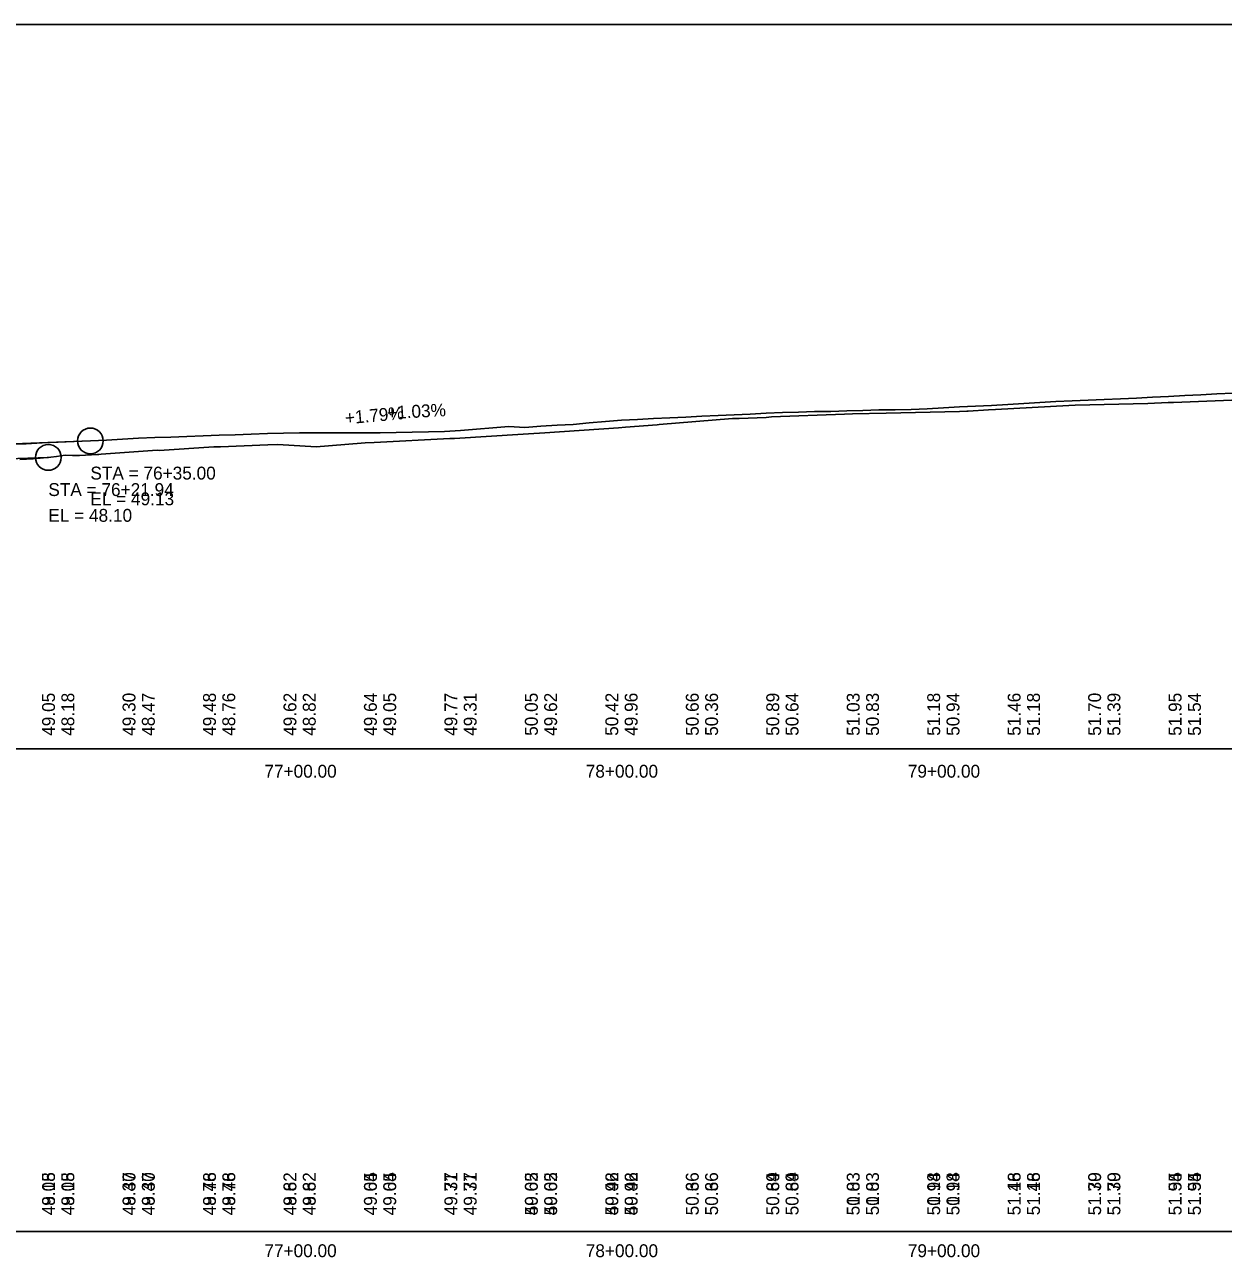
# Model space of a CAD drawing. Extents: x 3880794 to 3915434, y 287517 to 300173.
# Drawn here: x 3888152.9 to 3888525.3, y 297716.1 to 298099.2 of the extents above; entities that cross this region are included whole.
import ezdxf

# ---------------------------------------------------------------- set-up
doc = ezdxf.new("R2010")
doc.units = 0
for name, color, linetype in [('Level 1', 7, 'Continuous'), ('Level 2', 7, 'Continuous'), ('Level 30', 7, 'Continuous'), ('Level 31', 7, 'Continuous'), ('Level 32', 7, 'Continuous'), ('Level 62', 7, 'Continuous'), ('Level 63', 7, 'Continuous')]:
    doc.layers.add(name, color=color, linetype=linetype)

msp = doc.modelspace()

# ---------------------------------------------------------------- linework, layer by layer
at = {"layer": 'Level 1'}
for p, q in [((3888454.51, 297979.57), (3888477.27, 297980.88)), ((3888477.27, 297980.88), (3888479.27, 297980.91)), ((3888479.27, 297980.91), (3888501.82, 297981.48)), ((3888501.82, 297981.48), (3888508.1, 297981.73)), ((3888508.1, 297981.73), (3888509.82, 297981.78)), ((3888509.82, 297981.78), (3888533.14, 297982.7)), ((3888350.03, 297974.92), (3888372.84, 297976.79)), ((3888372.84, 297976.79), (3888374.91, 297976.82)), ((3888374.91, 297976.82), (3888383.28, 297977.13)), ((3888383.28, 297977.13), (3888384.96, 297977.28)), ((3888384.96, 297977.28), (3888407.59, 297978.13)), ((3888407.59, 297978.13), (3888410.04, 297978.24)), ((3888410.04, 297978.24), (3888420.58, 297978.5)), ((3888420.58, 297978.5), (3888443.34, 297979.03)), ((3888443.34, 297979.03), (3888445.58, 297979.08)), ((3888445.58, 297979.08), (3888446.03, 297979.09)), ((3888446.03, 297979.09), (3888452.37, 297979.45)), ((3888452.37, 297979.45), (3888454.51, 297979.57)), ((3888309.37, 297972.01), (3888314.47, 297972.36)), ((3888314.47, 297972.36), (3888337.33, 297973.92)), ((3888337.33, 297973.92), (3888339.57, 297974.08)), ((3888339.57, 297974.08), (3888349.44, 297974.88)), ((3888349.44, 297974.88), (3888350.03, 297974.92)), ((3888213.77, 297967.97), (3888228.46, 297968.58)), ((3888228.46, 297968.58), (3888231.56, 297968.71)), ((3888231.56, 297968.71), (3888243.46, 297968)), ((3888243.46, 297968), (3888257.41, 297969.12)), ((3888257.41, 297969.12), (3888258.68, 297969.19)), ((3888258.68, 297969.19), (3888261.5, 297969.34)), ((3888261.5, 297969.34), (3888284.97, 297970.56)), ((3888284.97, 297970.56), (3888286.46, 297970.6)), ((3888286.46, 297970.6), (3888307.75, 297971.91)), ((3888307.75, 297971.91), (3888309.37, 297972.01)), ((3888138.3, 297963.97), (3888160.24, 297964.71)), ((3888160.24, 297964.71), (3888161.02, 297964.78)), ((3888161.02, 297964.78), (3888162.78, 297965.02)), ((3888162.78, 297965.02), (3888165.44, 297965.39)), ((3888165.44, 297965.39), (3888167.71, 297965.28)), ((3888167.71, 297965.28), (3888168.39, 297965.32)), ((3888168.39, 297965.32), (3888169.57, 297965.28)), ((3888169.57, 297965.28), (3888169.87, 297965.29)), ((3888169.87, 297965.29), (3888175.48, 297965.6)), ((3888175.48, 297965.6), (3888175.94, 297965.66)), ((3888175.94, 297965.66), (3888176.69, 297965.72)), ((3888176.69, 297965.72), (3888194.04, 297966.95)), ((3888194.04, 297966.95), (3888194.67, 297966.89)), ((3888194.67, 297966.89), (3888211.62, 297967.97)), ((3888211.62, 297967.97), (3888213.77, 297967.97))]:
    msp.add_line(p, q, dxfattribs=at)
for points in [[(3888213.77, 297967.97), (3888228.46, 297968.58), (3888231.56, 297968.71), (3888243.46, 297968), (3888257.41, 297969.12), (3888258.68, 297969.19), (3888261.5, 297969.34), (3888284.97, 297970.56), (3888286.46, 297970.6), (3888307.75, 297971.91), (3888309.37, 297972.01), (3888314.47, 297972.36), (3888337.33, 297973.92), (3888339.57, 297974.08), (3888349.44, 297974.88), (3888350.03, 297974.92), (3888372.84, 297976.79), (3888374.91, 297976.82), (3888383.28, 297977.13), (3888384.96, 297977.28), (3888407.59, 297978.13), (3888410.04, 297978.24), (3888420.58, 297978.5), (3888443.34, 297979.03), (3888445.58, 297979.08), (3888446.03, 297979.09), (3888452.37, 297979.45), (3888454.51, 297979.57), (3888477.27, 297980.88), (3888479.27, 297980.91), (3888501.82, 297981.48), (3888508.1, 297981.73), (3888509.82, 297981.78), (3888533.14, 297982.7)], [(3888151.4, 297964.06), (3888155.49, 297964.25), (3888156.52, 297964.37), (3888161.02, 297964.78), (3888162.78, 297965.02), (3888165.44, 297965.39), (3888167.71, 297965.28), (3888168.39, 297965.32), (3888169.57, 297965.28), (3888169.87, 297965.29), (3888175.48, 297965.6), (3888175.94, 297965.66), (3888176.69, 297965.72), (3888194.04, 297966.95), (3888194.67, 297966.89), (3888211.62, 297967.97), (3888213.77, 297967.97)]]:
    msp.add_lwpolyline(points, dxfattribs=at)
msp.add_circle((3888160.24, 297964.71), 4, dxfattribs=at)
at = {"layer": 'Level 2'}
for p, q in [((3888508.3, 297983.67), (3888513.3, 297983.93)), ((3888513.3, 297983.93), (3888518.3, 297984.18)), ((3888518.3, 297984.18), (3888523.3, 297984.43)), ((3888523.3, 297984.43), (3888528.3, 297984.69)), ((3888433.3, 297979.79), (3888438.3, 297980.07)), ((3888438.3, 297980.07), (3888443.3, 297980.39)), ((3888443.3, 297980.39), (3888448.3, 297980.68)), ((3888448.3, 297980.68), (3888453.3, 297980.89)), ((3888453.3, 297980.89), (3888458.3, 297981.15)), ((3888458.3, 297981.15), (3888463.3, 297981.47)), ((3888463.3, 297981.47), (3888468.3, 297981.79)), ((3888468.3, 297981.79), (3888473.3, 297982.08)), ((3888473.3, 297982.08), (3888478.3, 297982.27)), ((3888478.3, 297982.27), (3888483.3, 297982.49)), ((3888483.3, 297982.49), (3888488.3, 297982.68)), ((3888488.3, 297982.68), (3888493.3, 297982.91)), ((3888493.3, 297982.91), (3888498.3, 297983.16)), ((3888498.3, 297983.16), (3888503.3, 297983.41)), ((3888503.3, 297983.41), (3888508.3, 297983.67)), ((3888333.3, 297975.92), (3888338.3, 297976.28)), ((3888338.3, 297976.28), (3888343.3, 297976.52)), ((3888343.3, 297976.52), (3888348.3, 297976.76)), ((3888348.3, 297976.76), (3888353.3, 297977)), ((3888353.3, 297977), (3888358.3, 297977.24)), ((3888358.3, 297977.24), (3888363.3, 297977.48)), ((3888363.3, 297977.48), (3888368.3, 297977.72)), ((3888368.3, 297977.72), (3888373.3, 297977.96)), ((3888373.3, 297977.96), (3888378.3, 297978.2)), ((3888378.3, 297978.2), (3888383.3, 297978.44)), ((3888383.3, 297978.44), (3888388.3, 297978.65)), ((3888388.3, 297978.65), (3888393.3, 297978.81)), ((3888393.3, 297978.81), (3888398.3, 297978.94)), ((3888398.3, 297978.94), (3888403.3, 297979.03)), ((3888403.3, 297979.03), (3888408.3, 297979.17)), ((3888408.3, 297979.17), (3888413.3, 297979.33)), ((3888413.3, 297979.33), (3888418.3, 297979.45)), ((3888418.3, 297979.45), (3888423.3, 297979.54)), ((3888423.3, 297979.54), (3888428.3, 297979.63)), ((3888428.3, 297979.63), (3888433.3, 297979.79)), ((3888228.3, 297972.15), (3888233.3, 297972.28)), ((3888233.3, 297972.28), (3888238.3, 297972.3)), ((3888238.3, 297972.3), (3888243.3, 297972.31)), ((3888243.3, 297972.31), (3888248.3, 297972.33)), ((3888248.3, 297972.33), (3888253.3, 297972.34)), ((3888253.3, 297972.34), (3888258.3, 297972.36)), ((3888258.3, 297972.36), (3888263.3, 297972.38)), ((3888263.3, 297972.38), (3888268.3, 297972.48)), ((3888268.3, 297972.48), (3888273.3, 297972.58)), ((3888273.3, 297972.58), (3888278.3, 297972.67)), ((3888278.3, 297972.67), (3888283.3, 297972.77)), ((3888283.3, 297972.77), (3888288.3, 297973.04)), ((3888288.3, 297973.04), (3888293.3, 297973.52)), ((3888293.3, 297973.52), (3888298.3, 297973.9)), ((3888298.3, 297973.9), (3888303.3, 297974.28)), ((3888303.3, 297974.28), (3888308.3, 297974)), ((3888308.3, 297974), (3888313.3, 297974.46)), ((3888313.3, 297974.46), (3888318.3, 297974.72)), ((3888318.3, 297974.72), (3888323.3, 297974.98)), ((3888323.3, 297974.98), (3888328.3, 297975.45)), ((3888328.3, 297975.45), (3888333.3, 297975.92)), ((3887438.3, 297942.07), (3888173.3, 297969.84)), ((3888173.3, 297969.84), (3888178.3, 297970.09)), ((3888178.3, 297970.09), (3888183.3, 297970.37)), ((3888183.3, 297970.37), (3888188.3, 297970.67)), ((3888188.3, 297970.67), (3888193.3, 297970.87)), ((3888193.3, 297970.87), (3888198.3, 297971.04)), ((3888198.3, 297971.04), (3888203.3, 297971.22)), ((3888203.3, 297971.22), (3888208.3, 297971.39)), ((3888208.3, 297971.39), (3888213.3, 297971.58)), ((3888213.3, 297971.58), (3888218.3, 297971.77)), ((3888218.3, 297971.77), (3888223.3, 297971.96)), ((3888223.3, 297971.96), (3888228.3, 297972.15))]:
    msp.add_line(p, q, dxfattribs=at)
msp.add_lwpolyline([(3888148.3, 297968.79), (3888153.3, 297968.97), (3888158.3, 297969.22), (3888163.3, 297969.46), (3888168.3, 297969.65), (3888173.3, 297969.84), (3888178.3, 297970.09), (3888183.3, 297970.37), (3888188.3, 297970.67), (3888193.3, 297970.87), (3888198.3, 297971.04), (3888203.3, 297971.22), (3888208.3, 297971.39), (3888213.3, 297971.58), (3888218.3, 297971.77), (3888223.3, 297971.96), (3888228.3, 297972.15), (3888233.3, 297972.28), (3888238.3, 297972.3), (3888243.3, 297972.31), (3888248.3, 297972.33), (3888253.3, 297972.34), (3888258.3, 297972.36), (3888263.3, 297972.38), (3888268.3, 297972.48), (3888273.3, 297972.58), (3888278.3, 297972.67), (3888283.3, 297972.77), (3888288.3, 297973.04), (3888293.3, 297973.52), (3888298.3, 297973.9), (3888303.3, 297974.28), (3888308.3, 297974), (3888313.3, 297974.46), (3888318.3, 297974.72), (3888323.3, 297974.98), (3888328.3, 297975.45), (3888333.3, 297975.92), (3888338.3, 297976.28), (3888343.3, 297976.52), (3888348.3, 297976.76), (3888353.3, 297977), (3888358.3, 297977.24), (3888363.3, 297977.48), (3888368.3, 297977.72), (3888373.3, 297977.96), (3888378.3, 297978.2), (3888383.3, 297978.44), (3888388.3, 297978.65), (3888393.3, 297978.81), (3888398.3, 297978.94), (3888403.3, 297979.03), (3888408.3, 297979.17), (3888413.3, 297979.33), (3888418.3, 297979.45), (3888423.3, 297979.54), (3888428.3, 297979.63), (3888433.3, 297979.79), (3888438.3, 297980.07), (3888443.3, 297980.39), (3888448.3, 297980.68), (3888453.3, 297980.89), (3888458.3, 297981.15), (3888463.3, 297981.47), (3888468.3, 297981.79), (3888473.3, 297982.08), (3888478.3, 297982.27), (3888483.3, 297982.49), (3888488.3, 297982.68), (3888493.3, 297982.91), (3888498.3, 297983.16), (3888503.3, 297983.41), (3888508.3, 297983.67), (3888513.3, 297983.93), (3888518.3, 297984.18), (3888523.3, 297984.43), (3888528.3, 297984.69)], dxfattribs=at)
msp.add_circle((3888173.3, 297969.84), 4, dxfattribs=at)
at = {"layer": 'Level 62'}
msp.add_lwpolyline([(3888038.3, 297874.19), (3888738.3, 297874.19), (3888738.3, 298099.19), (3888038.3, 298099.19)], close=True, dxfattribs=at)
msp.add_lwpolyline([(3888038.3, 297874.19), (3888738.3, 297874.19), (3888738.3, 298099.19), (3888038.3, 298099.19)], close=True, dxfattribs=at)
at = {"layer": 'Level 63'}
msp.add_line((3881538.3, 297724.19), (3896411.35, 297724.19), dxfattribs=at)

# ---------------------------------------------------------------- texts
at = {"layer": 'Level 2'}
msp.add_text('+1.03%', height=4, rotation=2.9406, dxfattribs=at).set_placement((3888265.58, 297976.58))
for s, p in [('STA = 76+35.00', (3888173.3, 297957.84)), ('EL = 49.13', (3888173.3, 297949.84))]:
    msp.add_text(s, height=4, dxfattribs=at).set_placement(p)
at = {"layer": 'Level 30'}
for s, p in [('77+00.00', (3888227.37, 297865.19)), ('77+00.00', (3888227.37, 297865.19)), ('78+00.00', (3888327.21, 297865.19)), ('78+00.00', (3888327.21, 297865.19)), ('79+00.00', (3888427.27, 297865.19)), ('79+00.00', (3888427.27, 297865.19)), ('77+00.00', (3888227.37, 297716.19)), ('77+00.00', (3888227.37, 297716.19)), ('78+00.00', (3888327.21, 297716.19)), ('78+00.00', (3888327.21, 297716.19)), ('79+00.00', (3888427.27, 297716.19)), ('79+00.00', (3888427.27, 297716.19))]:
    msp.add_text(s, height=4, dxfattribs=at).set_placement(p)
at = {"layer": 'Level 31'}
for s, rotation, p in [('+1.79%', 5.111, (3888252.57, 297974.98)), ('48.18', 90, (3888168.3, 297878.19)), ('48.47', 90, (3888193.3, 297878.19)), ('48.76', 90, (3888218.3, 297878.19)), ('48.82', 90, (3888243.3, 297878.19)), ('49.05', 90, (3888268.3, 297878.19)), ('49.31', 90, (3888293.3, 297878.19)), ('49.62', 90, (3888318.3, 297878.19)), ('49.96', 90, (3888343.3, 297878.19)), ('50.36', 90, (3888368.3, 297878.19)), ('50.64', 90, (3888393.3, 297878.19)), ('50.83', 90, (3888418.3, 297878.19)), ('50.94', 90, (3888443.3, 297878.19)), ('51.18', 90, (3888468.3, 297878.19)), ('51.39', 90, (3888493.3, 297878.19)), ('51.54', 90, (3888518.3, 297878.19)), ('50.64', 90, (3888387.3, 297729.19)), ('50.64', 90, (3888393.3, 297729.19)), ('50.94', 90, (3888437.3, 297729.19)), ('50.94', 90, (3888443.3, 297729.19)), ('51.54', 90, (3888512.3, 297729.19)), ('51.54', 90, (3888518.3, 297729.19)), ('48.18', 90, (3888162.3, 297729.19)), ('48.18', 90, (3888168.3, 297729.19)), ('48.47', 90, (3888187.3, 297729.19)), ('48.47', 90, (3888193.3, 297729.19)), ('48.76', 90, (3888212.3, 297729.19)), ('48.76', 90, (3888218.3, 297729.19)), ('48.82', 90, (3888237.3, 297729.19)), ('48.82', 90, (3888243.3, 297729.19)), ('49.05', 90, (3888262.3, 297729.19)), ('49.05', 90, (3888268.3, 297729.19)), ('49.31', 90, (3888287.3, 297729.19)), ('49.31', 90, (3888293.3, 297729.19)), ('49.62', 90, (3888312.3, 297729.19)), ('49.62', 90, (3888318.3, 297729.19)), ('49.96', 90, (3888337.3, 297729.19)), ('49.96', 90, (3888343.3, 297729.19)), ('50.36', 90, (3888362.3, 297729.19)), ('50.36', 90, (3888368.3, 297729.19)), ('50.83', 90, (3888412.3, 297729.19)), ('50.83', 90, (3888418.3, 297729.19)), ('51.18', 90, (3888462.3, 297729.19)), ('51.18', 90, (3888468.3, 297729.19)), ('51.39', 90, (3888487.3, 297729.19)), ('51.39', 90, (3888493.3, 297729.19))]:
    msp.add_text(s, height=4, rotation=rotation, dxfattribs=at).set_placement(p)
for s, p in [('STA = 76+21.94', (3888160.24, 297952.71)), ('EL = 48.10', (3888160.24, 297944.71))]:
    msp.add_text(s, height=4, dxfattribs=at).set_placement(p)
at = {"layer": 'Level 32'}
for s, p in [('49.05', (3888162.3, 297878.19)), ('49.30', (3888187.3, 297878.19)), ('49.48', (3888212.3, 297878.19)), ('49.62', (3888237.3, 297878.19)), ('49.64', (3888262.3, 297878.19)), ('49.77', (3888287.3, 297878.19)), ('50.05', (3888312.3, 297878.19)), ('50.42', (3888337.3, 297878.19)), ('50.66', (3888362.3, 297878.19)), ('50.89', (3888387.3, 297878.19)), ('51.03', (3888412.3, 297878.19)), ('51.18', (3888437.3, 297878.19)), ('51.46', (3888462.3, 297878.19)), ('51.70', (3888487.3, 297878.19)), ('51.95', (3888512.3, 297878.19)), ('49.64', (3888262.3, 297729.19)), ('49.64', (3888268.3, 297729.19)), ('49.05', (3888162.3, 297729.19)), ('49.05', (3888168.3, 297729.19)), ('49.30', (3888187.3, 297729.19)), ('49.30', (3888193.3, 297729.19)), ('49.48', (3888212.3, 297729.19)), ('49.48', (3888218.3, 297729.19)), ('49.62', (3888237.3, 297729.19)), ('49.62', (3888243.3, 297729.19)), ('49.77', (3888287.3, 297729.19)), ('49.77', (3888293.3, 297729.19)), ('50.05', (3888312.3, 297729.19)), ('50.05', (3888318.3, 297729.19)), ('50.42', (3888337.3, 297729.19)), ('50.42', (3888343.3, 297729.19)), ('50.66', (3888362.3, 297729.19)), ('50.66', (3888368.3, 297729.19)), ('50.89', (3888387.3, 297729.19)), ('50.89', (3888393.3, 297729.19)), ('51.03', (3888412.3, 297729.19)), ('51.03', (3888418.3, 297729.19)), ('51.18', (3888437.3, 297729.19)), ('51.18', (3888443.3, 297729.19)), ('51.46', (3888462.3, 297729.19)), ('51.46', (3888468.3, 297729.19)), ('51.70', (3888487.3, 297729.19)), ('51.70', (3888493.3, 297729.19)), ('51.95', (3888512.3, 297729.19)), ('51.95', (3888518.3, 297729.19))]:
    msp.add_text(s, height=4, rotation=90, dxfattribs=at).set_placement(p)

doc.saveas('drawing.dxf')
